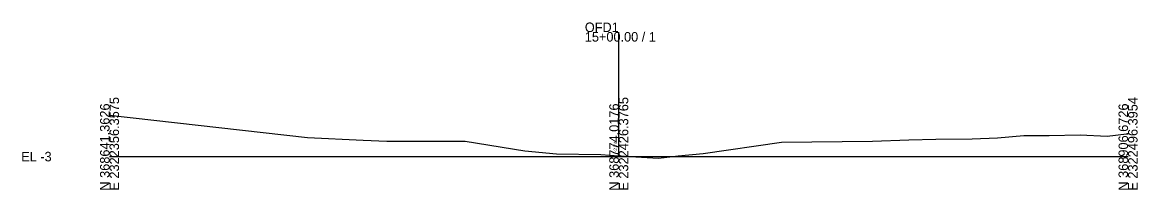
# Model space of a CAD drawing. Extents: x -26 to 303, y -10 to 14048.
# Drawn here: x -25.7 to 302.8, y 9990.3 to 10039.4 of the extents above; entities that cross this region are included whole.
import ezdxf

# ---------------------------------------------------------------- set-up
doc = ezdxf.new("R2010")
doc.units = 0
for name, color, linetype in [('RD_GPK_XS_Cell', 7, 'Continuous'), ('RD_XS_ExGround', 7, 'Continuous'), ('RD_XS_TX_Elev_EX', 7, 'Continuous')]:
    doc.layers.add(name, color=color, linetype=linetype)

msp = doc.modelspace()

# ---------------------------------------------------------------- linework, layer by layer
at = {"layer": 'RD_GPK_XS_Cell'}
for p, q in [((150, 10000), (150, 10036.57)), ((0, 10000), (150, 10000)), ((150, 10000), (300, 10000))]:
    msp.add_line(p, q, dxfattribs=at)
at = {"layer": 'RD_XS_ExGround'}
for p, q in [((0, 10012.19), (58.27, 10005.6)), ((58.27, 10005.6), (74.72, 10004.81)), ((74.72, 10004.81), (81.65, 10004.57)), ((81.65, 10004.57), (104.73, 10004.55)), ((104.73, 10004.55), (122.34, 10001.7)), ((174.9, 10000.93), (197.88, 10004.23)), ((197.88, 10004.23), (224.72, 10004.56)), ((224.72, 10004.56), (235.4, 10004.93)), ((235.4, 10004.93), (243.42, 10005.08)), ((243.42, 10005.08), (254.06, 10005.24)), ((254.06, 10005.24), (261.56, 10005.51)), ((261.56, 10005.51), (269.33, 10006.17)), ((269.33, 10006.17), (276.72, 10006.18)), ((276.72, 10006.18), (285.92, 10006.42)), ((285.92, 10006.42), (293.89, 10005.96)), ((293.89, 10005.96), (299.58, 10006.71)), ((299.58, 10006.71), (300, 10006.67)), ((122.34, 10001.7), (131.62, 10000.85)), ((131.62, 10000.85), (144.67, 10000.6)), ((144.67, 10000.6), (150, 10000.26)), ((167.5, 10000.19), (174.9, 10000.93)), ((150, 10000.26), (161.69, 9999.51)), ((161.69, 9999.51), (167.5, 10000.19))]:
    msp.add_line(p, q, dxfattribs=at)

# ---------------------------------------------------------------- texts
at = {"layer": 'RD_GPK_XS_Cell'}
for s, p in [('OFD1', (140, 10036.57)), ('15+00.00 / 1', (140, 10033.77)), ('EL -3', (-26, 9998.6))]:
    msp.add_text(s, height=2.8, dxfattribs=at).set_placement(p)
for s, p in [('E 2322356.3575', (2.8, 9990)), ('E 2322426.3765', (152.8, 9990)), ('E 2322496.3954', (302.8, 9990)), ('N 368641.3626', (0, 9990)), ('N 368774.0176', (150, 9990)), ('N 368906.6726', (300, 9990))]:
    msp.add_text(s, height=2.8, rotation=90, dxfattribs=at).set_placement(p)
at = {"layer": 'RD_XS_TX_Elev_EX'}
msp.add_text('-2.74', height=1, rotation=90, dxfattribs=at).set_placement((149.5, 10001.26))

doc.saveas('drawing.dxf')
